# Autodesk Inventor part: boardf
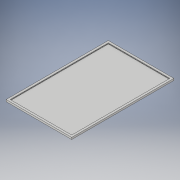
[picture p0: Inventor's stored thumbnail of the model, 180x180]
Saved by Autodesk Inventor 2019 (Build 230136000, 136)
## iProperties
Created: 2019-11
Part Number: boardf
Material: Generic
Document SubType Name: Sheet Metal
Designer: PRADYUMNA
Density: 1 g/cm^3
Sheet Metal Rule: Default_mm
Appearance: Default
Author: PRADYUMNA
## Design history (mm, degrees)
sketch "Sketch1"
  geometry: L1 (298.079, 573.895)-(-274.921, 573.895); L2 (-274.921, 573.895)-(-274.921, -319.105); L3 (-274.921, -319.105)-(298.079, -319.105); L4 (298.079, -319.105)-(298.079, 573.895); 1 further point
  constraints: 8 end point, 2 parallel, 1 horizontal, 1 perpendicular
  dimensions: "d0" = 893 distance of L3.end L1.start; "d1" = 573 distance of L1.start L1.end
extrude "Extrusion1" new body sketch "Sketch1" distance "d2" = 16; taper "d3" = 0 deg
sketch "Sketch2"
  geometry: L1 (-278.079, -553.895)-(254.921, -553.895); L2 (254.921, -553.895)-(254.921, 299.105); L3 (254.921, 299.105)-(-278.079, 299.105); L4 (-278.079, 299.105)-(-278.079, -553.895); L5 (-298.079, 319.105)-(-298.079, -573.895) reference; L6 (274.921, -573.895)-(274.921, 319.105) reference; L7 (274.921, 319.105)-(-298.079, 319.105) reference; L8 (-298.079, -573.895)-(274.921, -573.895) reference; 1 further point
  constraints: 8 end point, 2 parallel, 1 horizontal, 1 perpendicular
  dimensions: "d4" = 20 distance between parallel lines of L4 L5; "d5" = 20 distance between parallel lines of L6 L2; "d6" = 20 distance between parallel lines of L7 L3; "d7" = 20 distance between parallel lines of L1 L8
extrude "Extrusion2" cut sketch "Sketch2" distance "d8" = 5; taper "d9" = 0 deg
fillet "Fillet1" dims "d10" = 2
body "Solid1"
other parameters: "Thickness" = 0.5, "BendRadius" = 0.5 (= Thickness), "BendReliefWidth" = 0.5 (= Thickness), "BendReliefDepth" = 0.25 (= 0.5 x Thickness), "CornerReliefSize" = 2 (= 4 x Thickness), "SeamGap" = 0.01, "MinimumRemnant" = 1 (= 2 x Thickness), "TransitionRadius" = 0.5 (= BendRadius), "JacobiRadiusSize" = 0.5 (= BendRadius), "GapSize" = 0.5 (= Thickness)
